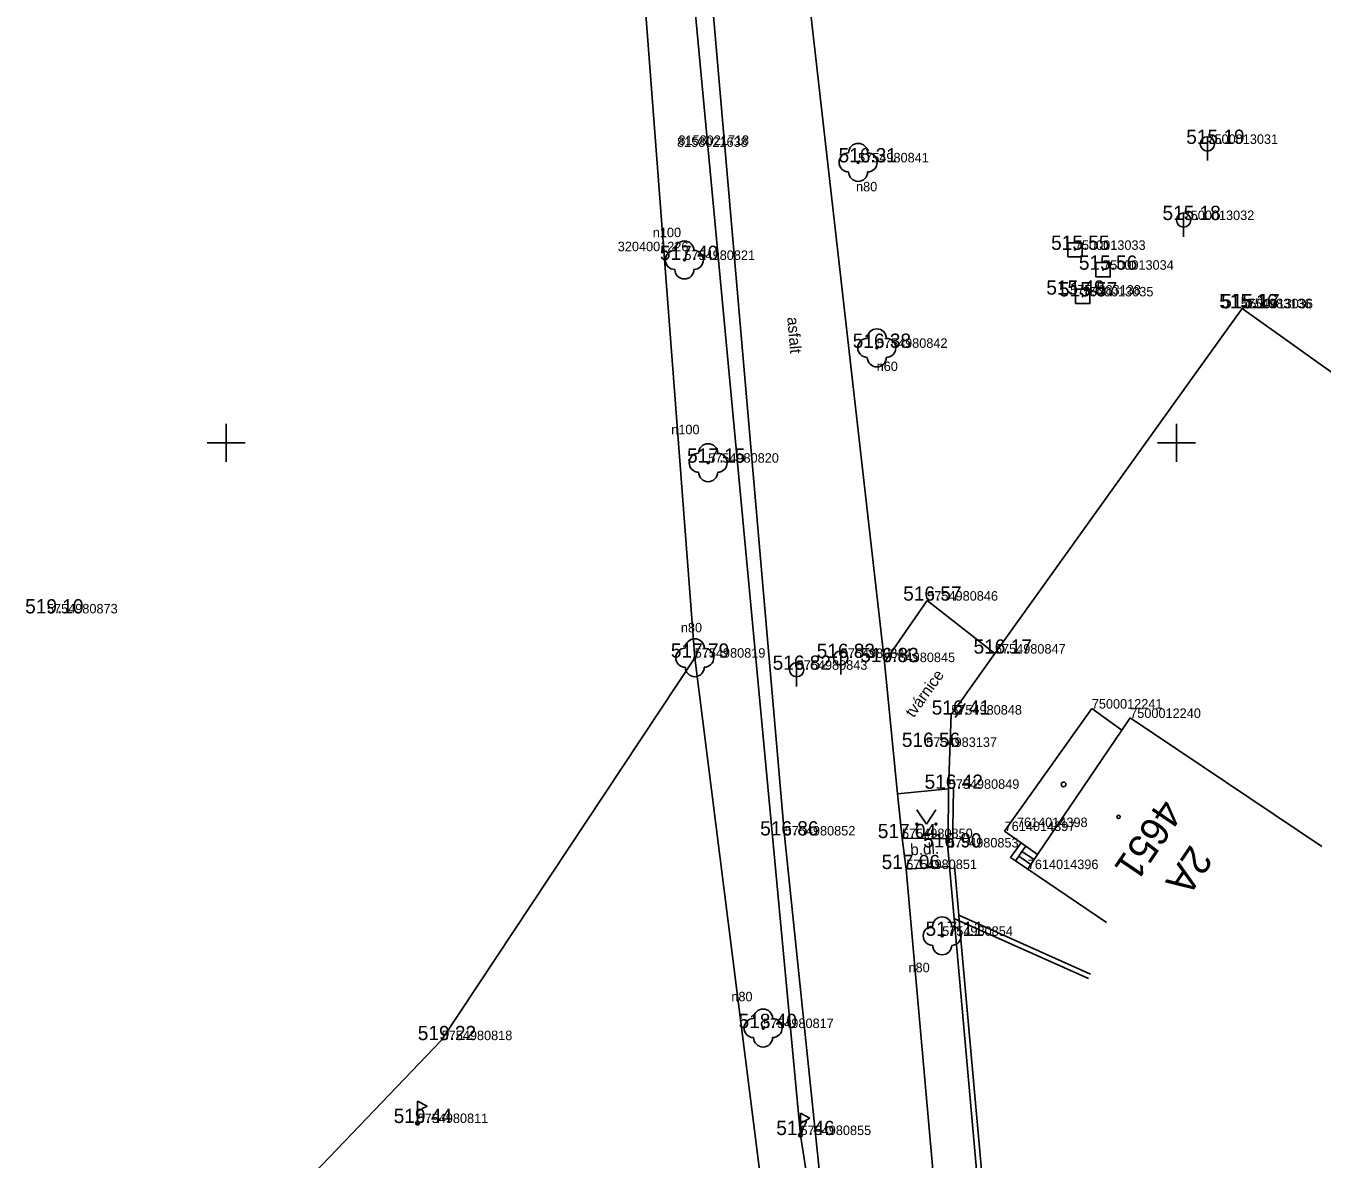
# Model space of a CAD drawing. Extents: x -669251 to -668549, y -1128351 to -1127698.
# Drawn here: x -669060.5 to -668992.3, y -1128087.7 to -1128028.1 of the extents above; entities that cross this region are included whole.
import ezdxf

# ---------------------------------------------------------------- set-up
doc = ezdxf.new("R2010")
doc.units = 0
for name, color, linetype in [('Vrstva 1', 7, 'Continuous'), ('Vrstva 10', 7, 'Continuous'), ('Vrstva 11', 7, 'Continuous'), ('Vrstva 14', 7, 'Continuous'), ('Vrstva 2', 7, 'Continuous'), ('Vrstva 22', 7, 'Continuous'), ('Vrstva 25', 7, 'Continuous'), ('Vrstva 26', 7, 'Continuous'), ('Vrstva 27', 7, 'Continuous'), ('Vrstva 3', 7, 'Continuous'), ('Vrstva 36', 7, 'Continuous'), ('Vrstva 40', 7, 'Continuous'), ('Vrstva 43', 7, 'Continuous'), ('Vrstva 44', 7, 'Continuous'), ('Vrstva 47', 7, 'Continuous'), ('Vrstva 5', 7, 'Continuous'), ('Vrstva 58', 7, 'Continuous'), ('Vrstva 61', 7, 'Continuous'), ('Vrstva 7', 7, 'Continuous'), ('Vrstva 8', 7, 'Continuous')]:
    doc.layers.add(name, color=color, linetype=linetype)

msp = doc.modelspace()

# ---------------------------------------------------------------- linework, layer by layer
at = {"layer": 'Vrstva 1'}
for p, q in [((-669026.28, -1128034.44), (-669026.28, -1128034.44)), ((-669026.21, -1128034.34), (-669026.21, -1128034.34)), ((-668998.38, -1128034.285), (-668998.38, -1128034.285)), ((-669016.755, -1128035.257), (-669016.755, -1128035.257)), ((-668999.633, -1128038.29), (-668999.633, -1128038.29)), ((-669029.4, -1128039.93), (-669029.4, -1128039.93)), ((-669005.352, -1128039.858), (-669005.352, -1128039.858)), ((-669025.895, -1128040.389), (-669025.895, -1128040.389)), ((-669003.869, -1128040.904), (-669003.869, -1128040.904)), ((-669005.6, -1128042.213), (-669005.6, -1128042.213)), ((-669004.94, -1128042.306), (-669004.94, -1128042.306)), ((-668996.627, -1128042.93), (-668996.627, -1128042.93)), ((-668996.547, -1128042.935), (-668996.547, -1128042.935)), ((-669015.773, -1128045.012), (-669015.773, -1128045.012)), ((-669024.644, -1128051.053), (-669024.644, -1128051.053)), ((-669013.117, -1128058.308), (-669013.117, -1128058.308)), ((-669059.426, -1128058.979), (-669059.426, -1128058.979)), ((-669009.558, -1128061.094), (-669009.558, -1128061.094)), ((-669025.352, -1128061.307), (-669025.352, -1128061.307)), ((-669017.67, -1128061.321), (-669017.67, -1128061.321)), ((-669015.372, -1128061.54), (-669015.372, -1128061.54)), ((-669019.987, -1128061.943), (-669019.987, -1128061.943)), ((-669011.856, -1128064.302), (-669011.856, -1128064.302)), ((-669004.463, -1128063.986), (-669004.463, -1128063.986)), ((-669002.444, -1128064.477), (-669002.444, -1128064.477)), ((-669013.168, -1128066), (-669013.168, -1128066)), ((-669011.993, -1128068.205), (-669011.993, -1128068.205)), ((-669020.621, -1128070.658), (-669020.621, -1128070.658)), ((-669009.048, -1128070.425), (-669009.048, -1128070.425)), ((-669008.402, -1128070.217), (-669008.402, -1128070.217)), ((-669014.447, -1128070.798), (-669014.447, -1128070.798)), ((-669012.032, -1128071.289), (-669012.032, -1128071.289)), ((-668992.366, -1128071.24), (-668992.366, -1128071.24)), ((-669014.223, -1128072.423), (-669014.223, -1128072.423)), ((-669007.831, -1128072.427), (-669007.831, -1128072.427)), ((-669012.334, -1128075.937), (-669012.334, -1128075.937)), ((-669021.755, -1128080.787), (-669021.755, -1128080.787)), ((-669038.666, -1128081.423), (-669038.666, -1128081.423)), ((-669039.932, -1128085.782), (-669039.932, -1128085.782)), ((-669019.787, -1128086.415), (-669019.787, -1128086.415))]:
    msp.add_line(p, q, dxfattribs=at)
at = {"layer": 'Vrstva 10'}
for p, q in [((-669020.621, -1128070.658), (-669025.231, -1128017.573)), ((-669020.289, -1128018.283), (-669015.372, -1128061.54)), ((-669015.372, -1128061.54), (-669013.117, -1128058.308)), ((-669013.117, -1128058.308), (-669009.558, -1128061.094)), ((-669015.372, -1128061.54), (-669014.679, -1128068.473)), ((-669014.679, -1128068.473), (-669011.993, -1128068.205)), ((-669014.679, -1128068.473), (-669014.447, -1128070.798)), ((-669017.465, -1128101.159), (-669020.621, -1128070.658)), ((-669014.447, -1128070.798), (-669014.223, -1128072.423)), ((-669012.026, -1128070.829), (-669014.447, -1128070.798)), ((-669011.943, -1128072.285), (-669014.223, -1128072.423)), ((-669014.223, -1128072.423), (-669011.864, -1128099.227))]:
    msp.add_line(p, q, dxfattribs=at)
at = {"layer": 'Vrstva 11'}
for p, q in [((-669008.731, -1128071.817), (-669008.18, -1128071.043)), ((-669008.135, -1128071.496), (-669007.936, -1128071.217)), ((-669008.731, -1128071.817), (-669008.483, -1128071.985)), ((-669008.483, -1128071.985), (-669008.309, -1128071.741)), ((-669008.483, -1128071.985), (-669007.831, -1128072.427)), ((-669008.309, -1128071.741), (-669008.135, -1128071.496)), ((-669008.309, -1128071.741), (-669007.663, -1128072.179)), ((-669008.135, -1128071.496), (-669007.494, -1128071.93))]:
    msp.add_line(p, q, dxfattribs=at)
at = {"layer": 'Vrstva 14'}
for p, q in [((-669019.787, -1128086.415), (-669026.23, -1128017.766)), ((-669025.352, -1128061.307), (-669028.259, -1128023.14)), ((-669038.666, -1128081.423), (-669025.352, -1128061.307)), ((-669020.634, -1128098.678), (-669025.352, -1128061.307)), ((-669047.339, -1128090.47), (-669038.666, -1128081.423)), ((-669017.465, -1128101.159), (-669019.787, -1128086.415))]:
    msp.add_line(p, q, dxfattribs=at)
at = {"layer": 'Vrstva 22'}
for centre in [(-669016.755, -1128035.257), (-669025.895, -1128040.389), (-669015.773, -1128045.012), (-669024.644, -1128051.053), (-669025.35, -1128061.31), (-669012.334, -1128075.937), (-669021.755, -1128080.787)]:
    msp.add_circle(centre, 0.05, dxfattribs=at)
for centre, start, end in [((-669016.755, -1128034.757), 0, 180), ((-669017.255, -1128035.257), 90, 270), ((-669016.255, -1128035.257), 270, 90), ((-669016.755, -1128035.757), 180, 0), ((-669025.895, -1128039.889), 0, 180), ((-669026.395, -1128040.389), 90, 270), ((-669025.395, -1128040.389), 270, 90), ((-669025.895, -1128040.889), 180, 0), ((-669015.773, -1128044.512), 0, 180), ((-669016.273, -1128045.012), 90, 270), ((-669015.273, -1128045.012), 270, 90), ((-669015.773, -1128045.512), 180, 0), ((-669024.644, -1128050.553), 0, 180), ((-669025.144, -1128051.053), 90, 270), ((-669024.144, -1128051.053), 270, 90), ((-669024.644, -1128051.553), 180, 0), ((-669025.35, -1128060.81), 0, 180), ((-669025.85, -1128061.31), 90, 270), ((-669024.85, -1128061.31), 270, 90), ((-669025.35, -1128061.81), 180, 0), ((-669012.834, -1128075.937), 90, 270), ((-669012.334, -1128075.437), 0, 180), ((-669011.834, -1128075.937), 270, 90), ((-669012.334, -1128076.437), 180, 0), ((-669022.255, -1128080.787), 90, 270), ((-669021.755, -1128080.287), 0, 180), ((-669021.255, -1128080.787), 270, 90), ((-669021.755, -1128081.287), 180, 0)]:
    msp.add_arc(centre, 0.5, start, end, dxfattribs=at)
at = {"layer": 'Vrstva 25'}
for p, q in [((-669039.932, -1128085.782), (-669039.932, -1128084.632)), ((-669039.932, -1128084.632), (-669039.432, -1128084.897)), ((-669039.432, -1128084.897), (-669039.932, -1128085.162)), ((-669019.79, -1128086.42), (-669019.79, -1128085.27)), ((-669019.79, -1128085.27), (-669019.29, -1128085.535)), ((-669019.29, -1128085.535), (-669019.79, -1128085.8))]:
    msp.add_line(p, q, dxfattribs=at)
for centre, radius in [((-669039.932, -1128085.782), 0.1), ((-669039.932, -1128085.782), 0.0348), ((-669019.79, -1128086.42), 0.1), ((-669019.79, -1128086.42), 0.0348)]:
    msp.add_circle(centre, radius, dxfattribs=at)
at = {"layer": 'Vrstva 26'}
for points in [[(-669005.727, -1128040.233), (-669004.977, -1128040.233), (-669004.977, -1128039.483), (-669005.727, -1128039.483)], [(-669004.244, -1128041.279), (-669003.494, -1128041.279), (-669003.494, -1128040.529), (-669004.244, -1128040.529)], [(-669005.315, -1128042.681), (-669004.565, -1128042.681), (-669004.565, -1128041.931), (-669005.315, -1128041.931)]]:
    msp.add_lwpolyline(points, close=True, dxfattribs=at)
for centre in [(-669005.352, -1128039.858), (-669003.869, -1128040.904), (-669004.94, -1128042.306)]:
    msp.add_circle(centre, 0.02, dxfattribs=at)
at = {"layer": 'Vrstva 27'}
for p, q in [((-668998.38, -1128033.91), (-668998.38, -1128035.16)), ((-668999.633, -1128037.915), (-668999.633, -1128039.165)), ((-669017.67, -1128060.945), (-669017.67, -1128062.195)), ((-669019.99, -1128061.565), (-669019.99, -1128062.815))]:
    msp.add_line(p, q, dxfattribs=at)
for centre in [(-668998.38, -1128034.285), (-668999.633, -1128038.29), (-669017.67, -1128061.32), (-669019.99, -1128061.94)]:
    msp.add_circle(centre, 0.375, dxfattribs=at)
at = {"layer": 'Vrstva 36'}
for p, q in [((-669013.661, -1128069.306), (-669013.161, -1128070.056)), ((-669013.161, -1128070.056), (-669012.661, -1128069.306))]:
    msp.add_line(p, q, dxfattribs=at)
for centre in [(-669013.661, -1128070.056), (-669012.661, -1128070.056)]:
    msp.add_circle(centre, 0.05, dxfattribs=at)
at = {"layer": 'Vrstva 5'}
for p, q in [((-669004.463, -1128063.986), (-669009.048, -1128070.425)), ((-669002.877, -1128065.115), (-669004.463, -1128063.986)), ((-669002.444, -1128064.477), (-669002.877, -1128065.115)), ((-668992.366, -1128071.24), (-669002.444, -1128064.477)), ((-669002.877, -1128065.115), (-669007.312, -1128071.661)), ((-669008.18, -1128071.043), (-669009.048, -1128070.425)), ((-669007.936, -1128071.217), (-669008.18, -1128071.043)), ((-669007.312, -1128071.661), (-669007.936, -1128071.217)), ((-669007.494, -1128071.93), (-669007.663, -1128072.179)), ((-669007.312, -1128071.661), (-669007.494, -1128071.93)), ((-669007.663, -1128072.179), (-669007.831, -1128072.427)), ((-669003.692, -1128075.232), (-669007.831, -1128072.427))]:
    msp.add_line(p, q, dxfattribs=at)
at = {"layer": 'Vrstva 58'}
for centre, radius in [((-669005.947, -1128067.973), 0.125), ((-669003.052, -1128069.679), 0.0875)]:
    msp.add_circle(centre, radius, dxfattribs=at)
at = {"layer": 'Vrstva 61'}
for p, q in [((-669050, -1128049), (-669050, -1128051)), ((-669000, -1128049), (-669000, -1128051)), ((-669051, -1128050), (-669049, -1128050)), ((-669001, -1128050), (-668999, -1128050))]:
    msp.add_line(p, q, dxfattribs=at)
at = {"layer": 'Vrstva 7'}
for p, q in [((-668999.46, -1128046.999), (-668996.547, -1128042.935)), ((-668996.547, -1128042.935), (-668974.262, -1128058.906)), ((-669009.558, -1128061.094), (-668999.46, -1128046.999)), ((-669011.331, -1128063.57), (-669011.856, -1128064.302)), ((-669011.652, -1128064.447), (-669011.127, -1128063.715)), ((-669011.993, -1128068.205), (-669012.026, -1128070.829)), ((-669011.782, -1128071.292), (-669011.743, -1128068.208)), ((-669012.026, -1128070.829), (-669012.032, -1128071.289)), ((-669011.699, -1128075.024), (-669011.943, -1128072.285)), ((-669011.462, -1128074.855), (-669011.693, -1128072.262)), ((-669011.437, -1128075.141), (-669011.462, -1128074.855)), ((-669004.537, -1128077.948), (-669011.462, -1128074.855)), ((-669011.699, -1128075.024), (-669011.437, -1128075.141)), ((-669009.588, -1128098.722), (-669011.699, -1128075.024)), ((-669011.437, -1128075.141), (-669004.639, -1128078.177)), ((-669009.339, -1128098.682), (-669011.437, -1128075.141))]:
    msp.add_line(p, q, dxfattribs=at)
at = {"layer": 'Vrstva 8'}
for p, q in [((-669009.558, -1128061.094), (-669011.331, -1128063.57)), ((-669011.856, -1128064.302), (-669011.993, -1128068.205)), ((-669012.032, -1128071.289), (-669011.943, -1128072.285))]:
    msp.add_line(p, q, dxfattribs=at)

# ---------------------------------------------------------------- texts
at = {"layer": 'Vrstva 2'}
for s, p in [('8158021638', (-669026.28, -1128034.44)), ('8158021718', (-669026.21, -1128034.34)), ('7500013031', (-668998.38, -1128034.285)), ('5754980841', (-669016.755, -1128035.257)), ('7500013032', (-668999.633, -1128038.29)), ('7500013033', (-669005.352, -1128039.858)), ('3204001226', (-669029.4, -1128039.93)), ('5754980821', (-669025.895, -1128040.389)), ('7500013034', (-669003.869, -1128040.904)), ('5754983138', (-669005.6, -1128042.213)), ('7500013035', (-669004.94, -1128042.306)), ('5754983136', (-668996.627, -1128042.93)), ('7500013036', (-668996.547, -1128042.935)), ('5754980842', (-669015.773, -1128045.012)), ('5754980820', (-669024.644, -1128051.053)), ('5754980846', (-669013.117, -1128058.308)), ('5754980873', (-669059.426, -1128058.979)), ('5754980819', (-669025.352, -1128061.307)), ('5754980844', (-669017.67, -1128061.321)), ('5754980845', (-669015.372, -1128061.54)), ('5754980847', (-669009.558, -1128061.094)), ('5754980843', (-669019.987, -1128061.943)), ('5754980848', (-669011.856, -1128064.302)), ('7500012241', (-669004.463, -1128063.986)), ('7500012240', (-669002.444, -1128064.477)), ('5754983137', (-669013.168, -1128066)), ('5754980849', (-669011.993, -1128068.205)), ('7614014397', (-669009.048, -1128070.425)), ('7614014398', (-669008.402, -1128070.217)), ('5754980852', (-669020.621, -1128070.658)), ('5754980850', (-669014.447, -1128070.798)), ('5754980853', (-669012.032, -1128071.289)), ('5754980851', (-669014.223, -1128072.423)), ('7614014396', (-669007.831, -1128072.427)), ('5754980854', (-669012.334, -1128075.937)), ('5754980817', (-669021.755, -1128080.787)), ('5754980818', (-669038.666, -1128081.423)), ('5754980811', (-669039.932, -1128085.782)), ('5754980855', (-669019.787, -1128086.415))]:
    msp.add_text(s, height=0.5, dxfattribs=at).set_placement(p)
at = {"layer": 'Vrstva 3'}
for s, p in [('515.19 ', (-668999.494, -1128034.285)), ('516.31 ', (-669017.784, -1128035.257)), ('515.18 ', (-669000.743, -1128038.29)), ('515.55 ', (-669006.604, -1128039.858)), ('517.40 ', (-669027.183, -1128040.389)), ('515.56 ', (-669005.143, -1128040.904)), ('515.49 ', (-669006.855, -1128042.213)), ('515.57 ', (-669006.192, -1128042.306)), ('515.16 ', (-668997.76, -1128042.93)), ('515.17 ', (-668997.657, -1128042.935)), ('516.38 ', (-669017.039, -1128045.012)), ('517.15 ', (-669025.754, -1128051.053)), ('516.57 ', (-669014.383, -1128058.308)), ('519.10 ', (-669060.574, -1128058.979)), ('517.79 ', (-669026.607, -1128061.307)), ('516.17 ', (-669010.682, -1128061.094)), ('516.82 ', (-669021.253, -1128061.943)), ('516.83 ', (-669018.936, -1128061.321)), ('516.83 ', (-669016.638, -1128061.54)), ('516.41 ', (-669012.885, -1128064.302)), ('516.56 ', (-669014.456, -1128066)), ('516.42 ', (-669013.259, -1128068.205)), ('516.86 ', (-669021.909, -1128070.658)), ('517.04 ', (-669015.721, -1128070.798)), ('516.90 ', (-669013.335, -1128071.289)), ('517.06 ', (-669015.519, -1128072.423)), ('517.11 ', (-669013.208, -1128075.937)), ('518.40 ', (-669023.043, -1128080.787)), ('519.22 ', (-669039.92, -1128081.423)), ('519.44 ', (-669041.186, -1128085.782)), ('517.46 ', (-669021.061, -1128086.415))]:
    msp.add_text(s, height=0.75, dxfattribs=at).set_placement(p)
at = {"layer": 'Vrstva 40'}
for s, rotation, p in [('asfalt', 274.96322, (-669020.488, -1128043.415)), ('tvárnice', 54.39452, (-669013.842, -1128064.499)), ('b.dl.', 3.46368, (-669013.995, -1128071.708))]:
    msp.add_text(s, height=0.6, rotation=rotation, dxfattribs=at).set_placement(p)
at = {"layer": 'Vrstva 43'}
msp.add_text('4651', height=1.5, rotation=235.88257, dxfattribs=at).set_placement((-669000.828, -1128068.637))
at = {"layer": 'Vrstva 44'}
msp.add_text('2A', height=1.5, rotation=235.88257, dxfattribs=at).set_placement((-668999.261, -1128071.091))
at = {"layer": 'Vrstva 47'}
for s, height, p in [('n80', 0.5, (-669016.866, -1128036.782)), ('n100', 0.5, (-669027.557, -1128039.191)), ('n60', 0.5, (-669015.781, -1128046.233)), ('n100', 0.5, (-669026.586, -1128049.557)), ('n80', 0.499, (-669026.079, -1128059.974)), ('n80', 0.5, (-669014.105, -1128077.855)), ('n80', 0.5, (-669023.426, -1128079.382))]:
    msp.add_text(s, height=height, dxfattribs=at).set_placement(p)

doc.saveas('drawing.dxf')
